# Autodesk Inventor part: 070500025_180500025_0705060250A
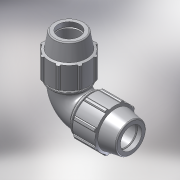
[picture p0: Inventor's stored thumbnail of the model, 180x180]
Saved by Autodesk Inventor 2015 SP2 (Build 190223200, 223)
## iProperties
Created: 2017-02
Part Number: 070500025_180500025_0705060250A
Material: PVC-Piping
Description: PLASSON 90° ELBOW 25-25
Document SubType Name: Modeling
Designer: KIM
Mass: 92.6774 g
Surface Area: 199.44 cm^2
Volume: 66.1981 cm^3
Density: 1.4 g/cm^3
Appearance: Smooth - White
Author: KIM
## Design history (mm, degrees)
derived "07050.ipt"
feature "Solid1::07050.ipt"
tag "TaggingFeature1"
body "Solid1"
other parameters: "d2" = 25, "d4" = 6.58333, "d5" = 19.75, "d7" = 54, "d9" = 11.28571, "d11" = 2.63333, "d13" = 120 deg, "d14" = 37.5, "d15" = 12 deg, "d16" = 46.98, "d18" = 1.25, "d19" = 35 deg, "d20" = 17.5 deg, "d21" = 50.22, "d23" = 0, "d25" = 360 deg, "d27" = 1.08, "d33" = 0.5, "d42" = 29.23, "d43" = 1.62, "d46" = 0.75, "d51" = 79, "d59" = 90 deg, "d63" = 58, "d64" = 22.5, "d67" = 40.5, "d68" = 2.63333, "d70" = 90 deg, "d71" = 3.75, "d_" = 25, "E_" = 54, "A_" = 79, "l_" = 58
